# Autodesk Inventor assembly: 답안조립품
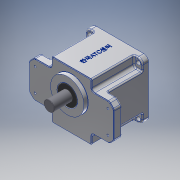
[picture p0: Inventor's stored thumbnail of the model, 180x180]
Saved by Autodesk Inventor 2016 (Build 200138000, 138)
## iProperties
Created: 2017-01
Part Number: 답안조립품
Material: 일반
Document SubType Name: Assembly
Designer: Owner
Author: Owner
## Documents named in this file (10)
- C:\Users\Owner\Desktop\470111V1005\답안조립품.iam
- C:\Users\Owner\Desktop\470111V1005\본체.ipt
- C:\Users\Owner\Desktop\470111V1005\메인축.ipt
- C:\Users\Owner\Desktop\470111V1005\베어링 608.ipt
- C:\Users\Owner\Desktop\470111V1005\베어링 6003.ipt
- C:\Users\Owner\Desktop\470111V1005\볼트 M4 x 10.ipt
- C:\Users\Owner\Desktop\470111V1005\서브축.ipt
- C:\Users\Owner\Desktop\470111V1005\오일실 8 22 7.ipt
- C:\Users\Owner\Desktop\470111V1005\오일실 17 32 8.ipt
- C:\Users\Owner\Desktop\470111V1005\커버.ipt
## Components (4 placed, 1 different names)
1. ISO 4762 M4 x 10:1
2. ISO 4762 M4 x 10:2
3. ISO 4762 M4 x 10:3
4. ISO 4762 M4 x 10:4
